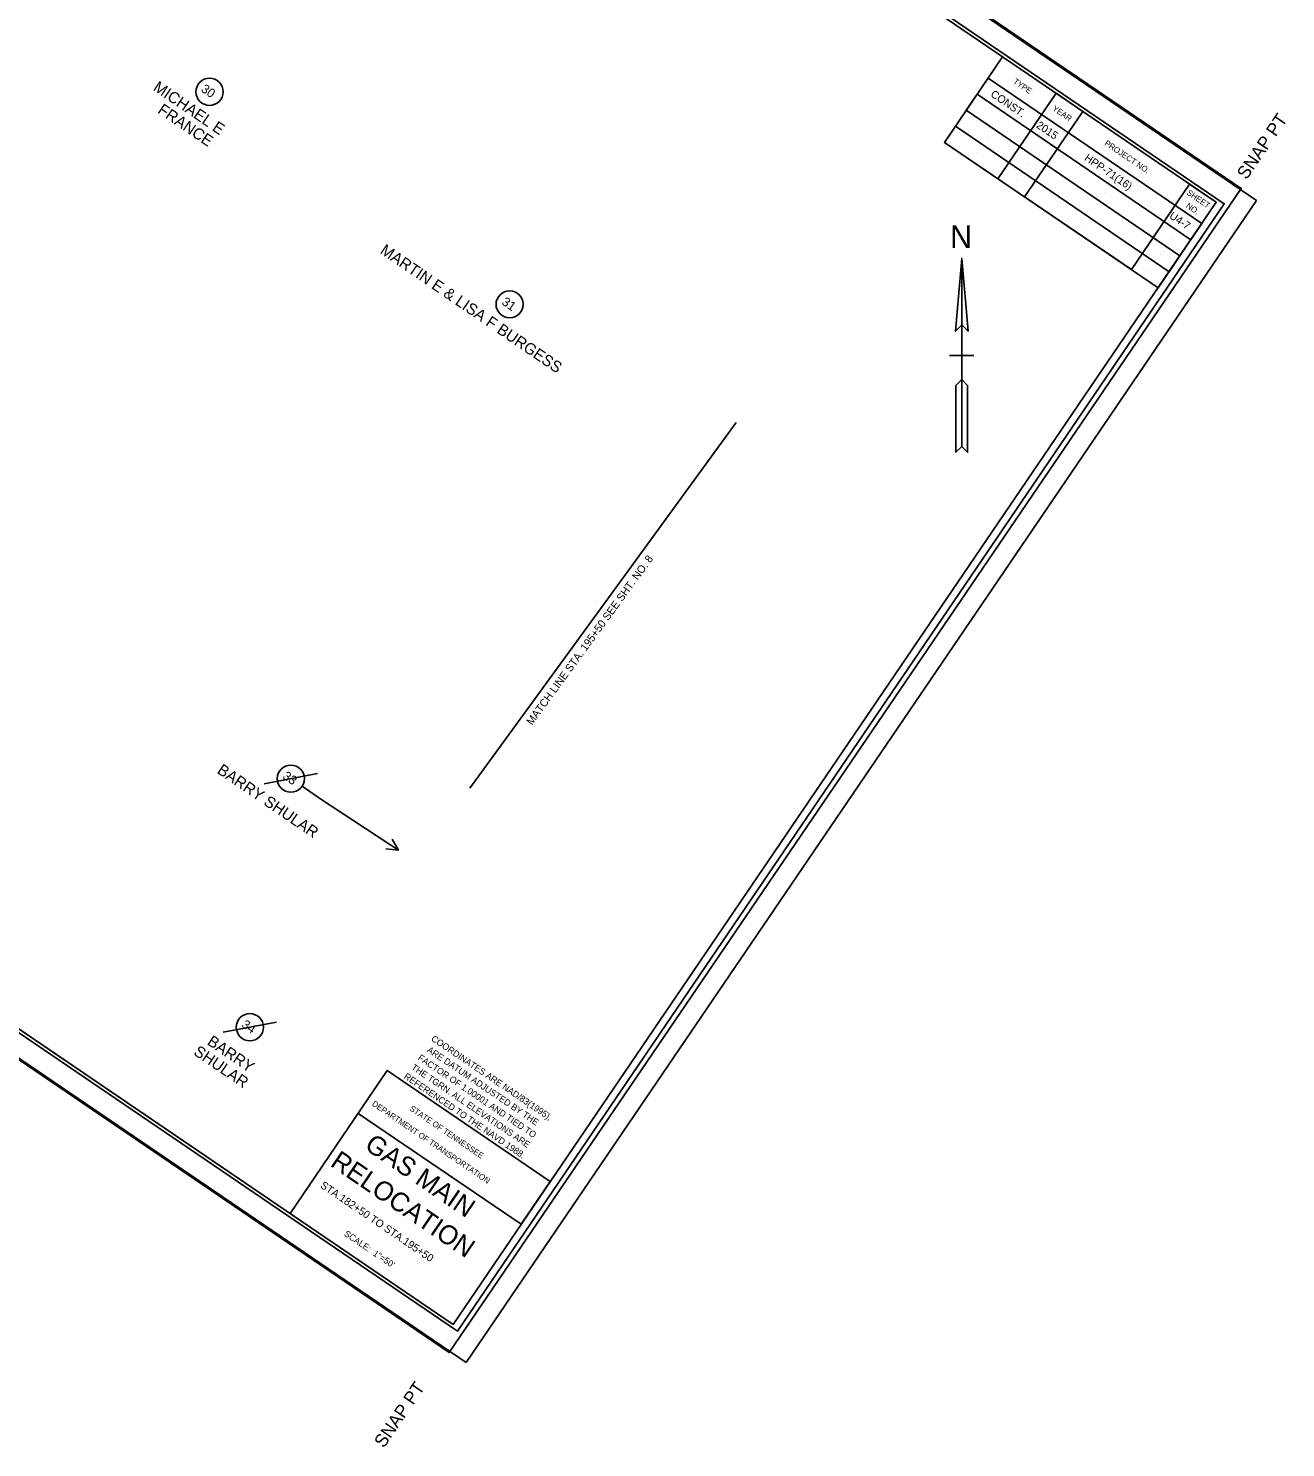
# Model space of a CAD drawing. Extents: x 2629906 to 2632029, y 567681 to 569670.
# Drawn here: x 2631056 to 2632029, y 567681 to 568779 of the extents above; entities that cross this region are included whole.
import ezdxf

# ---------------------------------------------------------------- set-up
doc = ezdxf.new("R2010")
doc.units = 0
for name, color, linetype in [('DESIGN - CENTERLINE - Proposed Text', 7, 'Continuous'), ('DESIGN - SCRATCH - User 1', 7, 'Continuous'), ('DESIGN - SHEET - Corner Text', 7, 'Continuous'), ('DESIGN - SHEET - Light Grid', 7, 'Continuous'), ('DESIGN - SHEET - Linework', 7, 'Continuous'), ('DESIGN - SHEET - Plot Shape', 7, 'Continuous'), ('SURVEY - PROPERTY - Owners', 7, 'Continuous'), ('SURVEY - PROPERTY - Tract Numbers', 7, 'Continuous')]:
    doc.layers.add(name, color=color, linetype=linetype)

msp = doc.modelspace()

# ---------------------------------------------------------------- linework, layer by layer
at = {"layer": 'DESIGN - CENTERLINE - Proposed Text'}
for p, q in [((2631778.1, 568525.9), (2631768.7, 568525.9)), ((2631787.6, 568525.9), (2631778.1, 568525.9))]:
    msp.add_line(p, q, dxfattribs=at)
for points in [[(2631778.1, 568600.9), (2631773.2, 568544.6), (2631778.1, 568549.5), (2631783, 568544.6), (2631778.1, 568600.9), (2631778.1, 568455.4), (2631782.7, 568450.9), (2631782.7, 568502.6), (2631778.1, 568507.2), (2631773.6, 568502.6), (2631773.6, 568450.9), (2631778.1, 568455.4)], [(2631397.5, 568191.1), (2631500.6, 568332.6), (2631603.6, 568474)]]:
    msp.add_lwpolyline(points, dxfattribs=at)
for points in [[(2631778.1, 568549.5), (2631783, 568544.6), (2631778.1, 568600.9)], [(2631773.6, 568450.9), (2631778.1, 568455.4), (2631778.1, 568507.2), (2631773.6, 568502.6)]]:
    msp.add_lwpolyline(points, close=True, dxfattribs=at)
at = {"layer": 'DESIGN - SCRATCH - User 1'}
for p, q in [((2631815, 568720.1), (2631815, 568720.1)), ((2631806.5, 568707.7), (2631806.5, 568707.7)), ((2631845.6, 568699.2), (2631845.6, 568699.2)), ((2631798.1, 568695.2), (2631798.1, 568695.2)), ((2631837.1, 568686.8), (2631837.1, 568686.8)), ((2631789.7, 568682.8), (2631789.7, 568682.8)), ((2631828.7, 568674.4), (2631828.7, 568674.4)), ((2631897.2, 568664.1), (2631897.2, 568664.1)), ((2631820.3, 568662), (2631820.3, 568662)), ((2631888.8, 568651.7), (2631888.8, 568651.7)), ((2631880.4, 568639.3), (2631880.4, 568639.3)), ((2631871.9, 568626.9), (2631871.9, 568626.9)), ((2631948.9, 568628.9), (2631948.9, 568628.9)), ((2631940.5, 568616.5), (2631940.5, 568616.5)), ((2631932, 568604.1), (2631932, 568604.1)), ((2631923.6, 568591.7), (2631923.6, 568591.7)), ((2631494.5, 568336.4), (2631494.5, 568336.4)), ((2631347.8, 567857.8), (2631347.8, 567857.8))]:
    msp.add_line(p, q, dxfattribs=at)
at = {"layer": 'DESIGN - SHEET - Light Grid'}
msp.add_lwpolyline([(2630011.2, 568707.4), (2631387.9, 567770.9), (2631981.3, 568643.2), (2630604.6, 569579.7)], close=True, dxfattribs=at)
at = {"layer": 'DESIGN - SHEET - Linework'}
for p, q in [((2630518, 569658.2), (2632006.3, 568645.8)), ((2629906.4, 568759.1), (2631394.7, 567746.7)), ((2632006.3, 568645.8), (2631394.7, 567746.7))]:
    msp.add_line(p, q, dxfattribs=at)
for points in [[(2630673.6, 569529.8), (2630083, 568661.6), (2631384.6, 567776.2), (2631975.1, 568644.4), (2630673.6, 569529.8)], [(2631809.8, 568756.9), (2631764.8, 568690.7), (2631930.1, 568578.2), (2631975.1, 568644.4), (2631954.5, 568658.4), (2631909.5, 568592.3), (2631826.8, 568648.5), (2631871.8, 568714.7), (2631851.1, 568728.7), (2631806.1, 568662.6), (2631764.8, 568690.7), (2631773.2, 568703.1), (2631938.6, 568590.6), (2631947, 568603), (2631781.6, 568715.5), (2631790.1, 568727.9), (2631955.5, 568615.4), (2631963.9, 568627.8), (2631798.5, 568740.3)], [(2631258.5, 567862), (2631333.6, 567972.5), (2631459.7, 567886.7), (2631437.2, 567853.6), (2631311.1, 567939.4)]]:
    msp.add_lwpolyline(points, dxfattribs=at)
at = {"layer": 'DESIGN - SHEET - Plot Shape'}
for points in [[(2630588.8, 569611.3), (2631994.4, 568655.1), (2631381.6, 567754.4), (2629976, 568710.6)], [(2630603.2, 569577.6), (2631975.1, 568644.4), (2631384.6, 567776.2), (2630012.6, 568709.5)]]:
    msp.add_lwpolyline(points, close=True, dxfattribs=at)
at = {"layer": 'SURVEY - PROPERTY - Tract Numbers'}
for p, q in [((2631238.4, 568194.5), (2631279.6, 568202.3)), ((2631206.6, 568002.2), (2631247.9, 568010.1))]:
    msp.add_line(p, q, dxfattribs=at)
for points in [[(2631282.2, 568182.6), (2631267.7, 568192.5)], [(2631342.3, 568143.1), (2631282.2, 568182.6)], [(2631337.4, 568151.5), (2631342.3, 568143.1), (2631332.6, 568144.2)]]:
    msp.add_lwpolyline(points, dxfattribs=at)
for centre in [(2631196.1, 568729.8), (2631428.3, 568565.4), (2631259, 568198.4), (2631227.3, 568006.1)]:
    msp.add_circle(centre, 10.5, dxfattribs=at)

# ---------------------------------------------------------------- texts
at = {"layer": 'DESIGN - CENTERLINE - Proposed Text'}
msp.add_text('N', height=17.7, dxfattribs=at).set_placement((2631769.1, 568608.9))
msp.add_text('MATCH LINE STA. 195+50 SEE SHT. NO. 8', height=6, rotation=53.918, dxfattribs=at).set_placement((2631445.6, 568239.3))
at = {"layer": 'DESIGN - SHEET - Corner Text'}
for s, height, rotation, p in [('TYPE', 4.5, 325.7738, (2631817.5, 568736.8)), ('CONST.', 6, 325.7738, (2631799.9, 568726.7)), ('YEAR', 4.5, 325.7738, (2631847.9, 568715.9)), ('  SNAP PT', 10, 55.7738, (2631994.4, 568655.1)), ('2015', 6, 325.7738, (2631835.3, 568702.6)), ('PROJECT NO.', 4.5, 325.7738, (2631888.2, 568689)), ('HPP-71(16)', 6, 325.7738, (2631872.5, 568677.3)), ('SHEET', 4.5, 325.7738, (2631951.8, 568650.7)), ('NO.', 4.5, 325.7738, (2631951.2, 568640.6)), ('U4-7', 6, 325.7738, (2631938.2, 568632.6)), ('COORDINATES ARE NAD/83(1995),', 5, 325.7738, (2631367.1, 567996.1)), ('FACTOR OF 1.00001 AND TIED TO', 5, 325.7738, (2631356.8, 567981.3)), ('ARE DATUM ADJUSTED BY THE', 5, 325.7738, (2631363.9, 567987.4)), ('THE TGRN. ALL ELEVATIONS ARE', 5, 325.7738, (2631351.7, 567973.9)), ('REFERENCED TO THE NAVD 1988.', 5, 325.7738, (2631346, 567966.9)), ('DEPARTMENT OF TRANSPORTATION', 4.5, 325.7738, (2631321.4, 567945.8)), ('STATE OF TENNESSEE', 4.5, 325.7738, (2631350.5, 567942.1)), ('GAS MAIN ', 14.76, 325.7738, (2631315.2, 567912.4)), ('RELOCATION', 14.76, 325.7738, (2631288.7, 567899.2)), ('STA.182+50 TO STA.195+50', 5.905, 325.7738, (2631281.3, 567882.4)), ('SCALE:  1"=50\'', 4.921, 325.7738, (2631299.7, 567845.2)), ('SNAP PT  ', 10, 55.7738, (2631331, 567680))]:
    msp.add_text(s, height=height, rotation=rotation, dxfattribs=at).set_placement(p)
at = {"layer": 'SURVEY - PROPERTY - Owners'}
for s, p in [('MICHAEL E', (2631151.8, 568731.5)), ('FRANCE', (2631155.3, 568714)), ('MARTIN E & LISA F BURGESS', (2631327.4, 568605.3)), ('BARRY SHULAR', (2631201.3, 568203.2)), ('BARRY', (2631193.6, 567993.2)), ('SHULAR', (2631183.1, 567985.3))]:
    msp.add_text(s, height=8.75, rotation=325.7738, dxfattribs=at).set_placement(p)
at = {"layer": 'SURVEY - PROPERTY - Tract Numbers'}
for s, p in [('30', (2631188.9, 568730.5)), ('31', (2631421.6, 568565.7)), ('33', (2631252.1, 568198.9)), ('34', (2631220.3, 568006.6))]:
    msp.add_text(s, height=7, rotation=325.7738, dxfattribs=at).set_placement(p)

doc.saveas('drawing.dxf')
